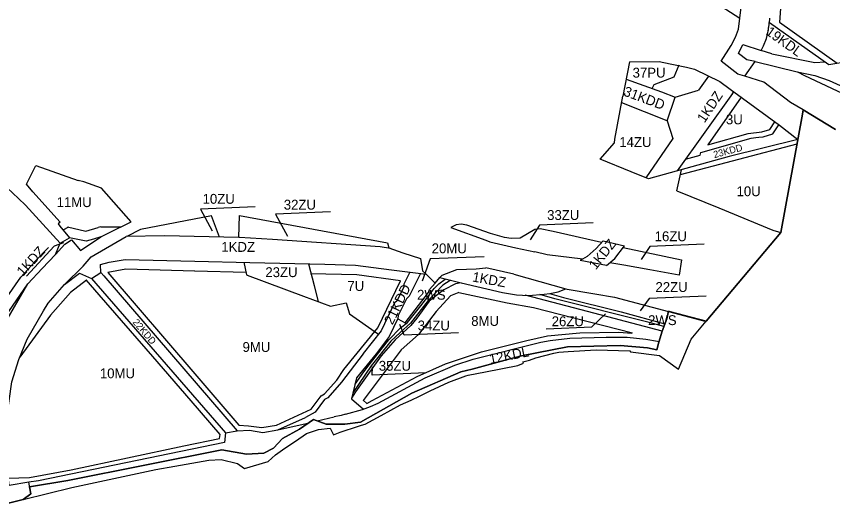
# Model space of a CAD drawing. Extents: x 7428203 to 7432868, y 5542672 to 5545406.
# Drawn here: x 7430591 to 7431420, y 5542851 to 5543351 of the extents above; entities that cross this region are included whole.
import ezdxf

# ---------------------------------------------------------------- set-up
doc = ezdxf.new("R2010")
doc.units = 0
for name, color, linetype in [('__LEGENDA_RAMKA_LOGO_PODZIAŁKA', 7, 'Continuous'), ('_GRANICA_MIASTA', 7, 'Continuous'), ('granicaBulwary', 7, 'Continuous'), ('MPZP_obowiazujace', 7, 'Continuous'), ('MPZP_uchwalone_nieobowiazujace jeszcze_SZRAF', 7, 'Continuous')]:
    doc.layers.add(name, color=color, linetype=linetype)

msp = doc.modelspace()

# ---------------------------------------------------------------- linework, layer by layer
at = {"layer": '__LEGENDA_RAMKA_LOGO_PODZIAŁKA'}
for p, q in [((7431291.44, 5543041.5), (7431367.08, 5543131.47)), ((7431255.26, 5543051.11), (7431291.44, 5543041.5)), ((7431246.47, 5543031.32), (7431251.22, 5543044.16)), ((7431243.09, 5543020.46), (7431246.47, 5543031.32)), ((7431231.73, 5543014.72), (7431241.17, 5543012.46)), ((7431241.17, 5543012.46), (7431243.09, 5543020.46)), ((7430604.51, 5542873.47), (7430643.41, 5542879.94)), ((7430605.65, 5542866.37), (7430604.51, 5542873.47)), ((7430598.08, 5542860.73), (7430605.65, 5542866.37))]:
    msp.add_line(p, q, dxfattribs=at)
for points in [[(7431367.08, 5543131.47), (7431389.13, 5543251.74), (7431389.74, 5543255.95), (7431422.59, 5543236.25)], [(7431251.22, 5543044.16), (7431253.22, 5543051.65), (7431255.26, 5543051.11)], [(7431090.85, 5543003.15), (7431103.88, 5543006.49), (7431150.57, 5543015.69), (7431204.07, 5543016.85), (7431231.73, 5543014.72)], [(7430892.85, 5542941.69), (7430905.6, 5542937.27), (7430924.37, 5542937.08), (7430940.43, 5542939.04), (7430992.42, 5542968.63), (7431042.11, 5542990.27), (7431053.76, 5542992.92), (7431090.85, 5543003.15)], [(7430824.69, 5542906.55), (7430842.4, 5542907.83), (7430852.28, 5542912.65), (7430861.32, 5542922.47), (7430878.57, 5542931.99), (7430892.85, 5542941.69)], [(7430643.41, 5542879.94), (7430799.83, 5542911.15), (7430824.69, 5542906.55)], [(7430559.44, 5542851.36), (7430598.08, 5542860.73)]]:
    msp.add_lwpolyline(points, dxfattribs=at)
at = {"layer": '_GRANICA_MIASTA'}
for p, q in [((7431325.38, 5543348.66), (7431298.04, 5543366.23)), ((7431321.19, 5543329.86), (7431324.03, 5543337.93)), ((7431353.79, 5543334.17), (7431355.52, 5543344.49)), ((7431316.69, 5543321.39), (7431321.19, 5543329.86)), ((7431352.37, 5543328.62), (7431353.79, 5543334.17)), ((7431306.4, 5543305.6), (7431316.69, 5543321.39)), ((7431358.01, 5543312.85), (7431347.25, 5543316.46)), ((7431213.56, 5543304.68), (7431206.88, 5543269.82)), ((7431213.56, 5543304.68), (7431243.49, 5543305.15)), ((7431243.49, 5543305.15), (7431254.85, 5543302.79)), ((7431323.55, 5543292.27), (7431306.4, 5543305.6)), ((7431341.18, 5543305.28), (7431341.19, 5543305.27)), ((7431341.18, 5543305.28), (7431383.66, 5543294.77)), ((7431254.85, 5543302.79), (7431271.5, 5543299.33)), ((7431271.5, 5543299.33), (7431279.54, 5543297.28)), ((7431293.73, 5543290.32), (7431283.49, 5543276.04)), ((7431330.51, 5543290.18), (7431323.55, 5543292.27)), ((7431349.89, 5543284.33), (7431330.51, 5543290.17)), ((7431376.85, 5543263.57), (7431349.89, 5543284.33)), ((7431260, 5543268.97), (7431283.49, 5543276.04)), ((7431317.91, 5543272.57), (7431261.85, 5543194.02)), ((7431315.62, 5543277.06), (7431365.63, 5543240.49)), ((7431198.58, 5543226.16), (7431206.88, 5543269.82)), ((7431251.59, 5543245.01), (7431205.63, 5543263.2)), ((7431251.59, 5543245.01), (7431260, 5543268.97)), ((7431389.74, 5543255.95), (7431376.85, 5543263.57)), ((7431389.74, 5543255.95), (7431389.13, 5543251.74)), ((7431422.59, 5543236.25), (7431389.74, 5543255.95)), ((7431389.13, 5543251.74), (7431367.08, 5543131.47)), ((7431251.59, 5543245.01), (7431257.32, 5543227.04)), ((7431358.96, 5543231.63), (7431364.89, 5543241.03)), ((7431365.63, 5543240.49), (7431384.39, 5543225.92)), ((7431349.26, 5543228.73), (7431358.96, 5543231.63)), ((7431183.85, 5543206.02), (7431198.16, 5543222.76)), ((7431198.16, 5543222.76), (7431198.58, 5543226.16)), ((7431257.32, 5543227.04), (7431230.21, 5543187.02)), ((7431285.94, 5543212.75), (7431336.86, 5543227.45)), ((7431384.39, 5543225.92), (7431314.6, 5543208.76)), ((7431336.86, 5543227.45), (7431341.76, 5543227.85)), ((7431341.76, 5543227.85), (7431344.92, 5543228.22)), ((7431344.92, 5543228.22), (7431349.26, 5543228.73)), ((7431215.33, 5543193.01), (7431183.85, 5543206.02)), ((7431314.6, 5543208.76), (7431232.92, 5543185.93)), ((7431270.33, 5543205.9), (7431285.05, 5543210.25)), ((7431285.05, 5543210.25), (7431285.94, 5543212.75)), ((7430601.28, 5543180.63), (7430611.05, 5543199.66)), ((7430611.05, 5543199.66), (7430653.75, 5543184.51)), ((7431232.92, 5543185.93), (7431215.33, 5543193.01)), ((7431261.47, 5543174.02), (7431266.16, 5543195.22)), ((7430607.74, 5543173), (7430601.28, 5543180.63)), ((7430659.57, 5543182.95), (7430653.75, 5543184.51)), ((7430677.6, 5543176.57), (7430659.57, 5543182.95)), ((7430607.74, 5543173), (7430635.51, 5543141.93)), ((7430707.62, 5543142.34), (7430677.6, 5543176.57)), ((7430600.23, 5543159.37), (7430593.17, 5543166.03)), ((7430635.65, 5543120.86), (7430600.23, 5543159.37)), ((7430635.51, 5543141.93), (7430633.66, 5543140.45)), ((7430633.66, 5543140.45), (7430635.22, 5543138.17)), ((7430684.85, 5543131.29), (7430707.62, 5543142.34)), ((7430635.22, 5543138.17), (7430645.16, 5543126.35)), ((7430677.01, 5543127.2), (7430684.85, 5543131.29)), ((7431367.08, 5543131.47), (7431291.44, 5543041.5)), ((7430635.65, 5543120.86), (7430645.16, 5543126.35)), ((7431186.78, 5543123.21), (7431208.53, 5543117.96)), ((7430630.9, 5543109.34), (7430635.65, 5543120.86)), ((7430983.55, 5543111.1), (7430983.34, 5543111)), ((7430821.94, 5543101.35), (7430824.74, 5543088.54)), ((7430887.81, 5543099.81), (7430893.4, 5543077.69)), ((7431190.22, 5543098.15), (7431163.5, 5543103.05)), ((7430667.34, 5543085.03), (7430676.71, 5543091.03)), ((7430990.62, 5543091.31), (7430984.53, 5543079.17)), ((7431096.12, 5543089.18), (7431149.02, 5543074.34)), ((7430679.85, 5543087.55), (7430815.4, 5542930.37)), ((7430893.4, 5543077.69), (7430897.52, 5543061.36)), ((7430984.77, 5543077.03), (7430977.25, 5543061.98)), ((7430984.53, 5543079.17), (7430984.77, 5543077.03)), ((7431009.32, 5543070.83), (7431010.38, 5543073.82)), ((7431024.93, 5543073.58), (7431010.13, 5543061.85)), ((7431010.38, 5543073.82), (7431016.2, 5543080.32)), ((7431036.96, 5543079.41), (7431024.93, 5543073.58)), ((7431042.59, 5543080.43), (7431036.96, 5543079.41)), ((7431148.15, 5543074.59), (7431178.33, 5543069.24)), ((7430985.79, 5543040.06), (7431009.32, 5543070.83)), ((7431191.42, 5543046.12), (7431107.57, 5543067.9)), ((7431178.33, 5543069.24), (7431198.11, 5543066.03)), ((7431198.11, 5543066.03), (7431291.4, 5543041.44)), ((7430975.09, 5543060.13), (7430961.28, 5543031.71)), ((7430977.25, 5543061.98), (7430975.09, 5543060.13)), ((7431010.13, 5543061.85), (7430997.71, 5543044.54)), ((7430929.18, 5543049.19), (7430958.66, 5543028.39)), ((7430978.31, 5543044.01), (7430985.79, 5543040.06)), ((7430997.71, 5543044.54), (7430991.67, 5543037.29)), ((7431246.47, 5543031.32), (7431191.42, 5543046.12)), ((7430961.28, 5543031.71), (7430943.17, 5543008.79)), ((7430991.67, 5543037.29), (7430975.56, 5543022.7)), ((7431246.47, 5543031.32), (7431243.36, 5543021.07)), ((7430975.56, 5543022.7), (7430961.55, 5543006.48)), ((7430961.55, 5543006.48), (7430935.2, 5542970.07)), ((7430935.2, 5542970.07), (7430931.42, 5542963.5)), ((7430894.31, 5542949.4), (7430884.44, 5542943.89)), ((7430856.36, 5542931.3), (7430884.44, 5542943.89)), ((7430896.4, 5542940.46), (7430913.61, 5542944.4)), ((7430920.71, 5542945.93), (7430913.61, 5542944.4)), ((7430925.14, 5542947.16), (7430920.71, 5542945.93)), ((7430856.36, 5542931.3), (7430888.32, 5542938.61)), ((7430803.34, 5542928.16), (7430815.4, 5542930.37)), ((7430815.4, 5542930.37), (7430827.74, 5542930.92)), ((7430827.74, 5542930.92), (7430841.19, 5542928.82)), ((7430841.19, 5542928.82), (7430856.36, 5542931.3)), ((7430598.08, 5542860.73), (7430559.44, 5542851.36))]:
    msp.add_line(p, q, dxfattribs=at)
for points in [[(7431324.03, 5543337.93), (7431326.85, 5543360.24), (7431328.85, 5543390.18)], [(7431355.55, 5543344.75), (7431415.94, 5543301.93)], [(7431341.18, 5543305.28), (7431332.65, 5543306.96), (7431324.08, 5543313.32), (7431328.38, 5543322.38), (7431347.25, 5543316.46)], [(7431347.25, 5543316.46), (7431349.6, 5543320.92), (7431352.37, 5543328.62)], [(7431415.94, 5543301.93), (7431436.35, 5543305.54), (7431463.65, 5543312.41), (7431492.57, 5543328.57), (7431547.32, 5543289.35), (7431547.5, 5543281)], [(7431358.01, 5543312.85), (7431401.47, 5543304.12), (7431411.95, 5543304.76)], [(7431330.51, 5543290.17), (7431341.18, 5543305.28)], [(7431279.54, 5543297.28), (7431305.18, 5543284.7), (7431315.62, 5543277.06)], [(7431383.66, 5543294.77), (7431401.55, 5543290.86), (7431416.06, 5543285.83), (7431464.51, 5543263.85), (7431478.05, 5543260.69), (7431487.44, 5543259.4)], [(7431384.15, 5543294.67), (7431390.98, 5543291.05), (7431457.43, 5543259.96)], [(7431210.22, 5543287.25), (7431245.79, 5543274.19), (7431260, 5543268.97)], [(7431317.91, 5543272.57), (7431319.24, 5543274.42)], [(7430532.69, 5543191.3), (7430581.89, 5543176.93), (7430593.17, 5543166.03)], [(7431261.47, 5543174.02), (7431304.04, 5543156.49), (7431358.91, 5543134.14), (7431367.08, 5543131.47)], [(7430797.41, 5543127.03), (7430789.08, 5543148.63), (7430717.22, 5543134.56), (7430703.28, 5543127.55)], [(7430817.05, 5543126.67), (7430817.5, 5543148.92), (7430967.97, 5543121.29), (7430969.19, 5543115.92), (7430983.55, 5543111.1)], [(7431185.13, 5543121.38), (7431136.14, 5543132.76), (7431122.82, 5543135.29), (7431117.5, 5543134.55), (7431102.38, 5543125.96), (7431093.26, 5543125.56), (7431086.75, 5543126.47), (7431072.47, 5543130.6), (7431048.41, 5543139.12), (7431042.77, 5543140.18), (7431037.51, 5543139.55), (7431032.17, 5543136.76), (7431067.51, 5543123.71)], [(7430630.9, 5543109.34), (7430640.21, 5543119.63), (7430647.09, 5543124.22)], [(7430640.04, 5543078.8), (7430658.82, 5543097.28), (7430666.9, 5543106.9), (7430702.7, 5543127.54)], [(7430677.01, 5543127.2), (7430669.48, 5543124.99), (7430661.95, 5543122.77), (7430645.16, 5543126.35)], [(7430647.09, 5543124.22), (7430656.36, 5543113.5), (7430677.01, 5543127.2)], [(7430970.76, 5543115.39), (7430960.39, 5543117.22), (7430851.24, 5543124.43), (7430817.52, 5543126.66), (7430817.05, 5543126.67), (7430741.53, 5543128.06), (7430702.7, 5543127.54)], [(7431067.51, 5543123.71), (7431071.7, 5543122.2), (7431098.03, 5543116.18), (7431117.41, 5543111.93)], [(7431186.78, 5543123.21), (7431179.59, 5543115.24), (7431170.41, 5543107.24), (7431163.5, 5543103.05)], [(7431190.22, 5543098.15), (7431198.61, 5543105.32), (7431208.53, 5543117.96)], [(7431207.19, 5543116.25), (7431266.4, 5543103.96), (7431263.97, 5543088.4), (7431234.21, 5543093.57), (7431207.77, 5543098.32), (7431193.41, 5543100.88)], [(7430630.9, 5543109.34), (7430617.2, 5543095.14), (7430602.9, 5543079.56)], [(7430983.34, 5543111), (7431001.31, 5543105.39), (7431003.25, 5543092.61), (7431007.1, 5543089.25)], [(7431166.06, 5543104.6), (7431129.89, 5543109.1), (7431117.41, 5543111.93)], [(7430679.85, 5543087.55), (7430676.71, 5543091.03), (7430676.51, 5543098.98), (7430685.45, 5543101.53), (7430701.58, 5543104.29), (7430772.34, 5543102.49)], [(7430772.34, 5543102.49), (7430828.15, 5543101.21), (7430904.17, 5543099.42), (7430935.38, 5543098.34), (7430972.06, 5543093.63), (7431007.1, 5543089.25)], [(7431001.41, 5543089.96), (7430989.76, 5543067.08), (7430987.26, 5543064.33), (7430978.78, 5543047.23), (7430978.41, 5543044.22), (7430969.4, 5543026.05), (7430956.42, 5543008.56), (7430936.4, 5542983.96), (7430931.26, 5542962.87), (7430943.63, 5542952.43)], [(7431007.1, 5543089.25), (7431016.2, 5543080.32), (7431020.97, 5543085.89)], [(7431020.97, 5543085.89), (7431023.39, 5543088.32), (7431038.38, 5543094.04), (7431057.86, 5543094.64), (7431067.68, 5543095.64)], [(7431096.12, 5543089.18), (7431067.68, 5543095.64)], [(7430824.74, 5543088.54), (7430825.32, 5543088.32), (7430882.47, 5543066.96), (7430909.9, 5543056.76)], [(7431032.15, 5543083.02), (7431031.49, 5543082.8), (7431024.11, 5543078.22), (7431009.22, 5543062.48), (7430991.34, 5543039.66), (7430980.73, 5543030.07), (7430971.11, 5543021.38), (7430951.1, 5542996.28), (7430932.76, 5542969)], [(7430934.89, 5542977.75), (7430943.98, 5542990.11), (7430949.36, 5542997.43), (7430961.57, 5543012.9), (7430969.35, 5543022.76), (7430980.93, 5543034.86), (7430988.13, 5543040.13), (7431001.57, 5543057.3), (7431011.01, 5543069.36), (7431015.2, 5543074.71), (7431019.97, 5543079.64), (7431026.4, 5543084.28), (7431026.64, 5543084.4)], [(7431020.91, 5543085.82), (7431042.59, 5543080.43), (7431084.62, 5543070.77), (7431098.68, 5543068.41), (7431110.93, 5543067.71), (7431127, 5543068.88), (7431132.51, 5543069.6), (7431141.19, 5543071.49), (7431149.02, 5543074.34)], [(7430539.24, 5542989.88), (7430556.31, 5543012.63), (7430602.9, 5543079.56)], [(7430539.24, 5542989.88), (7430557.16, 5542950.48), (7430563.6, 5542992.83), (7430564.95, 5543001.72), (7430577.95, 5543036.88), (7430602.9, 5543079.56)], [(7431248.28, 5543036.2), (7431233.58, 5543040.14), (7431137.74, 5543064.42), (7431122.53, 5543068.55)], [(7431132.25, 5543069.57), (7431146.49, 5543065.7), (7431205.07, 5543051.02), (7431249.23, 5543038.79)], [(7430909.9, 5543056.76), (7430926.03, 5543060.4), (7430929.18, 5543049.19)], [(7430925.14, 5542947.16), (7430942.4, 5542951.98), (7430950.72, 5542954.98), (7430958.32, 5542958.46), (7431006.2, 5542984.06), (7431036.32, 5542997.13), (7431054.65, 5543003.21), (7431123.37, 5543020.34), (7431132.91, 5543021.98), (7431152.9, 5543024.33), (7431189.8, 5543025.51), (7431211.08, 5543025.27), (7431229.97, 5543023.49), (7431241.8, 5543021.48), (7431243.29, 5543021.09)], [(7430943.17, 5543008.79), (7430943.12, 5543008.61), (7430921.15, 5542979.67), (7430907.13, 5542963.77), (7430903.98, 5542962.06), (7430894.31, 5542949.4)], [(7430598.07, 5542860.73), (7430605.65, 5542866.37), (7430603.73, 5542878.38)]]:
    msp.add_lwpolyline(points, dxfattribs=at)
msp.add_lwpolyline([(7430802.24, 5542918.55), (7430613.59, 5542879.57), (7430603.73, 5542878.38), (7430583.89, 5542874.93), (7430579.15, 5542914.59), (7430581.28, 5542943.83), (7430586.64, 5542980.02), (7430593.65, 5543002.63), (7430602.22, 5543023.27), (7430618.72, 5543051.98), (7430623.29, 5543059.94), (7430640.04, 5543078.8), (7430655.04, 5543090.28), (7430667.34, 5543085.03), (7430803.34, 5542928.16)], close=True, dxfattribs=at)
msp.add_ellipse((7431131.75, 5543374.32), major_axis=(0, 234.86), ratio=0.960164, start_param=4.54608, end_param=4.604918, dxfattribs=at)
at = {"layer": 'granicaBulwary'}
for points in [[(7430833.66, 5543157.71), (7430777.9, 5543155.44), (7430789.97, 5543133.19)], [(7430910.03, 5543152.51), (7430854.27, 5543150.25), (7430866.34, 5543128)], [(7431176.46, 5543141.31), (7431122.26, 5543139.11), (7431112.6, 5543124.09)], [(7430639.05, 5543121.1), (7430629.58, 5543117.83), (7430601.38, 5543087.24)], [(7431289.24, 5543119.74), (7431234.21, 5543117.5), (7431225.29, 5543104.09)], [(7431066.07, 5543106.97), (7431011.02, 5543104.73), (7431002.96, 5543082.18)], [(7431291.32, 5543066.84), (7431233.48, 5543064.5), (7431224.43, 5543052.18)], [(7431129.06, 5543033.86), (7431175.34, 5543035.74), (7431189.08, 5543048.91)], [(7431039.78, 5543029.7), (7430984.73, 5543027.46), (7430980.47, 5543038.11)], [(7431007.17, 5542989.06), (7430952.12, 5542986.83), (7430952.49, 5542995.15)]]:
    msp.add_lwpolyline(points, dxfattribs=at)
at = {"layer": 'MPZP_obowiazujace'}
for p, q in [((7431291.44, 5543041.5), (7431255.26, 5543051.11)), ((7431251.22, 5543044.16), (7431246.47, 5543031.32)), ((7431246.47, 5543031.32), (7431243.09, 5543020.46)), ((7431231.73, 5543014.72), (7431204.07, 5543016.85)), ((7431241.17, 5543012.46), (7431231.73, 5543014.72)), ((7431243.09, 5543020.46), (7431241.17, 5543012.46)), ((7431090.85, 5543003.15), (7431053.76, 5542992.92)), ((7431042.11, 5542990.27), (7430992.42, 5542968.63)), ((7431053.76, 5542992.92), (7431042.11, 5542990.27)), ((7430892.85, 5542941.69), (7430878.57, 5542931.99)), ((7430905.6, 5542937.27), (7430892.85, 5542941.69)), ((7430924.37, 5542937.08), (7430905.6, 5542937.27)), ((7430799.83, 5542911.15), (7430643.41, 5542879.94)), ((7430824.69, 5542906.55), (7430799.83, 5542911.15)), ((7430643.41, 5542879.94), (7430604.51, 5542873.47)), ((7430604.51, 5542873.47), (7430605.65, 5542866.37)), ((7430598.08, 5542860.73), (7430647.46, 5542872.71)), ((7430605.65, 5542866.37), (7430598.08, 5542860.73))]:
    msp.add_line(p, q, dxfattribs=at)
for points in [[(7431255.26, 5543051.11), (7431253.22, 5543051.65), (7431251.22, 5543044.16)], [(7430647.46, 5542872.71), (7430732.73, 5542891.16), (7430752.12, 5542894.55), (7430786.59, 5542900.57), (7430798.88, 5542901.25), (7430815.65, 5542897.26), (7430822.74, 5542892.01), (7430846.6, 5542899.22), (7430853.99, 5542905.92), (7430863.71, 5542912.75), (7430874.29, 5542920.01), (7430885.57, 5542927.74), (7430897.93, 5542931.8), (7430909.65, 5542932.97), (7430912.97, 5542926.14), (7430919.7, 5542929.09), (7430938.41, 5542934.95), (7430941.31, 5542935.94), (7430945.17, 5542937.22), (7430961.44, 5542945.84), (7430981.02, 5542956.65), (7430991.87, 5542961.42), (7431000.22, 5542965.66), (7431011.08, 5542971.03), (7431030.19, 5542979.74), (7431047.37, 5542986.02), (7431049.63, 5542986.69), (7431067.47, 5542990.3), (7431100.14, 5542996.71), (7431105.8, 5542998.99), (7431105.28, 5543000.35), (7431111.94, 5543002.21), (7431118.57, 5543004.26), (7431136.61, 5543009.28), (7431141.58, 5543010.05), (7431151.33, 5543010.71), (7431179.79, 5543012.66), (7431213.77, 5543011.39), (7431214.4, 5543010.36), (7431243.99, 5543006.85), (7431263.28, 5542992.8), (7431276.18, 5543023.34), (7431291.44, 5543041.5)], [(7431204.07, 5543016.85), (7431150.57, 5543015.69), (7431103.88, 5543006.49), (7431090.85, 5543003.15)], [(7430992.42, 5542968.63), (7430940.43, 5542939.04), (7430924.37, 5542937.08)], [(7430878.57, 5542931.99), (7430861.32, 5542922.47), (7430852.28, 5542912.65)], [(7430852.28, 5542912.65), (7430842.4, 5542907.83), (7430824.69, 5542906.55)]]:
    msp.add_lwpolyline(points, dxfattribs=at)
at = {"layer": 'MPZP_uchwalone_nieobowiazujace jeszcze_SZRAF'}
for p, q in [((7431365.58, 5543344.99), (7431424.16, 5543303.46)), ((7431326.92, 5543268.8), (7431292.99, 5543220.43)), ((7431383.47, 5543221.23), (7431265.07, 5543189.99)), ((7430638.77, 5543134.2), (7430644.42, 5543137.46)), ((7430676.88, 5543137.2), (7430697.6, 5543137.48)), ((7430610, 5543102.09), (7430623.71, 5543116.28)), ((7430595.53, 5543086.32), (7430609.83, 5543101.9)), ((7430958.13, 5543034.82), (7430980.89, 5543082.72)), ((7430943.05, 5542961.3), (7430946.81, 5542957.94))]:
    msp.add_line(p, q, dxfattribs=at)
for points in [[(7431371.53, 5543495.49), (7431369.17, 5543476.66), (7431369.05, 5543442.73), (7431368.76, 5543387.51), (7431365.58, 5543344.99)], [(7431236.48, 5543277.61), (7431238.49, 5543281.87), (7431258.66, 5543289.72), (7431264.03, 5543301.76)], [(7431292.99, 5543220.43), (7431333.96, 5543232.21), (7431347.95, 5543233.61), (7431355.97, 5543236.01), (7431361.15, 5543244.02)], [(7430643.15, 5543137.19), (7430661.56, 5543133.08), (7430674.19, 5543136.8)], [(7430772.09, 5543092.5), (7430702.31, 5543094.27), (7430683.97, 5543091.13)], [(7430683.97, 5543091.13), (7430772.25, 5542988.26), (7430816.89, 5542936.24), (7430826.75, 5542935.3), (7430840.39, 5542933.76), (7430855.19, 5542936.17), (7430890.34, 5542952.44), (7430900.65, 5542965.94), (7430903.97, 5542967.74), (7430916.33, 5542981.72), (7430923.68, 5542992.47), (7430958.11, 5543034.86)], [(7430823.98, 5543090.87), (7430772.11, 5543092.5)], [(7430980.89, 5543082.72), (7430936.81, 5543088.55), (7430889.67, 5543089.76)], [(7430534.59, 5543000.35), (7430548.21, 5543018.49), (7430595.53, 5543086.32)], [(7430582.67, 5542882.44), (7430604.39, 5542882.87), (7430646.89, 5542890.7), (7430761.21, 5542915.18), (7430797.42, 5542922.66), (7430798.11, 5542926.47), (7430768.53, 5542960.68), (7430729.57, 5543005.62), (7430675.05, 5543068.5), (7430662.1, 5543083.43)], [(7430662.31, 5543083.39), (7430646.07, 5543070.77), (7430625.77, 5543047.86), (7430594.73, 5543005.07)], [(7431040.24, 5543070.71), (7431031.64, 5543067.47), (7431017.28, 5543051.28), (7430999.44, 5543028.12), (7430981.61, 5543012.38), (7430943.02, 5542961.14)], [(7431116.08, 5543055.25), (7431089.24, 5543059.89), (7431040.36, 5543070.47)], [(7431216.49, 5543029.32), (7431156.97, 5543044.69), (7431116.08, 5543055.25)], [(7430946.74, 5542958), (7430952.21, 5542961.16), (7430998.01, 5542985.35), (7431026.59, 5542998.36), (7431063.22, 5543010.58), (7431109.42, 5543022.1), (7431130.33, 5543026.61), (7431163.22, 5543029.66), (7431202.76, 5543030.36), (7431215.89, 5543029.48)]]:
    msp.add_lwpolyline(points, dxfattribs=at)
for centre, radius, start, end in [((7430677.02, 5543127.02), 10.18, 90.78146, 106.13423), ((7430594.53, 5543115.76), 20.65, 317.82616, 318.5335)]:
    msp.add_arc(centre, radius, start, end, dxfattribs=at)

# ---------------------------------------------------------------- texts
at = {"layer": 'granicaBulwary'}
for s, height, rotation, p in [('19KDL', 10, 324.41991, (7431350.97, 5543333.33)), ('31KDD', 10, 339.63572, (7431206.61, 5543270.86)), ('1KDZ', 10, 56.09819, (7431289.63, 5543242.21)), ('23KDD', 7, 15.00022, (7431299.63, 5543207.03)), ('1KDZ', 10, 359.7657, (7430799.12, 5543112.05)), ('1KDZ', 10, 51.42116, (7431179.18, 5543093.06)), ('1KDZ', 10, 47.58201, (7430597.8, 5543086.55)), ('1KDZ', 10, 349.72192, (7431053.4, 5543081.99)), ('21KDD', 10, 64.02136, (7430972.88, 5543037.21)), ('22KDD', 7, 310.52396, (7430708.7, 5543040.18)), ('12KDL', 10, 11.20677, (7431072.09, 5542998.14))]:
    msp.add_text(s, height=height, rotation=rotation, dxfattribs=at).set_placement(p)
for s, p in [('37PU', (7431216.64, 5543288.8)), ('3U', (7431311.35, 5543241.4)), ('14ZU', (7431203.08, 5543218.35)), ('10U', (7431322.13, 5543168.44)), ('11MU', (7430631.94, 5543157.41)), ('10ZU', (7430780.14, 5543160.76)), ('32ZU', (7430862.56, 5543154.84)), ('33ZU', (7431129.88, 5543144.36)), ('16ZU', (7431239.02, 5543122.77)), ('20MU', (7431012.68, 5543110.54)), ('23ZU', (7430843.85, 5543086.35)), ('7U', (7430927.09, 5543072.32)), ('22ZU', (7431239.84, 5543071.29)), ('2WS', (7430997.84, 5543063.41)), ('2WS', (7431232.37, 5543037.64)), ('34ZU', (7430998.45, 5543032.26)), ('8MU', (7431052.83, 5543036.84)), ('26ZU', (7431134.49, 5543036.51)), ('9MU', (7430820.71, 5543010.42)), ('35ZU', (7430958.99, 5542991.34)), ('10MU', (7430675.88, 5542983.71))]:
    msp.add_text(s, height=10, dxfattribs=at).set_placement(p)

doc.saveas('drawing.dxf')
